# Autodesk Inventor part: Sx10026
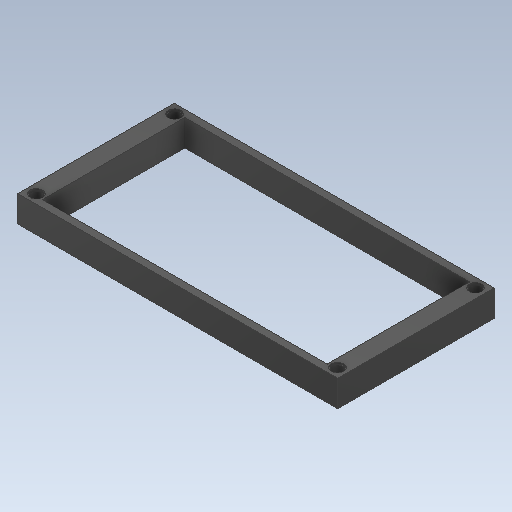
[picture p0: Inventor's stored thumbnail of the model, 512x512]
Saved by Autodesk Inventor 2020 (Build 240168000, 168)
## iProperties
Created: 2021-02
Part Number: Sx10026
Material: Generico
Document SubType Name: Modeling
Designer: zambolin
Density: 1 g/cm^3
Appearance: Default
Author: zambolin
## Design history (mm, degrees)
feature "Solido2"
node "Solido1"
